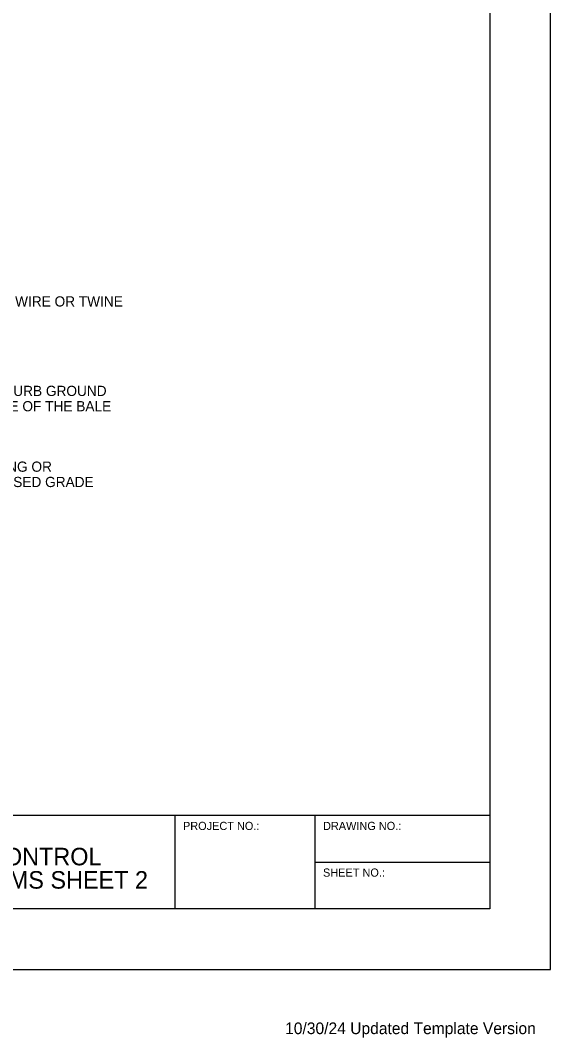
# Model space of a CAD drawing. Extents: x 0 to 2.83, y -0.06 to 1.83.
# Drawn here: x 2.379 to 2.833, y -0.058 to 0.813 of the extents above; entities that cross this region are included whole.
import ezdxf

# ---------------------------------------------------------------- set-up
doc = ezdxf.new("R2010")
doc.units = 0
for name, color, linetype in [('BDR_Inner_Perimeter', 7, 'Continuous'), ('BDR_Scale_As_Noted', 7, 'Continuous'), ('BDR_Title_Block', 7, 'Continuous'), ('Default', 7, 'Continuous'), ('Edge_of_Truck_Apron', 7, 'Continuous')]:
    doc.layers.add(name, color=color, linetype=linetype)

msp = doc.modelspace()

# ---------------------------------------------------------------- linework, layer by layer
at = {"layer": 'BDR_Inner_Perimeter'}
msp.add_lwpolyline([(0.13539, 1.78125), (2.78123, 1.78125), (2.78123, 0.05208), (0.13539, 0.05208)], close=True, dxfattribs=at)
at = {"layer": 'BDR_Scale_As_Noted'}
msp.add_lwpolyline([(0, 0), (2.83333, 0), (2.83333, 1.83333), (0, 1.83333)], close=True, dxfattribs=at)
msp.add_lwpolyline([(0, 0), (2.83333, 0), (2.83333, 1.83333), (0, 1.83333)], close=True, dxfattribs=at)
at = {"layer": 'BDR_Title_Block'}
for p, q in [((2.78123, 0.13208), (0.13539, 0.13208)), ((2.51123, 0.13208), (2.51123, 0.05208)), ((2.63123, 0.13208), (2.63123, 0.05208)), ((2.63123, 0.09208), (2.78123, 0.09208))]:
    msp.add_line(p, q, dxfattribs=at)

# ---------------------------------------------------------------- texts
for s, height, p in [('PROJECT NO.:', 0.007, (2.51823, 0.11958)), ('DRAWING NO.:', 0.007, (2.63823, 0.11958)), ('SEDIMENTATION CONTROL ', 0.015, (2.17981, 0.08933)), ('DOUBLE ROW SYSTEMS SHEET 2 ', 0.015, (2.16056, 0.06933)), ('SHEET NO.:', 0.007, (2.63823, 0.07958))]:
    msp.add_text(s, height=height, dxfattribs=at).set_placement(p)
at = {"layer": 'Default'}
msp.add_text('10/30/24 Updated Template Version', height=0.01, dxfattribs=at).set_placement((2.60576, -0.05536))
at = {"layer": 'Edge_of_Truck_Apron'}
for s, p in [('BINDING WIRE OR TWINE', (2.32237, 0.56822)), ('DO NOT DISTURB GROUND', (2.2974, 0.49153)), ('ON BACKSIDE OF THE BALE', (2.2974, 0.47841)), ('EXISTING OR ', (2.33049, 0.4266)), ('PROPOSED GRADE', (2.33049, 0.41347))]:
    msp.add_text(s, height=0.00875, dxfattribs=at).set_placement(p)

doc.saveas('drawing.dxf')
